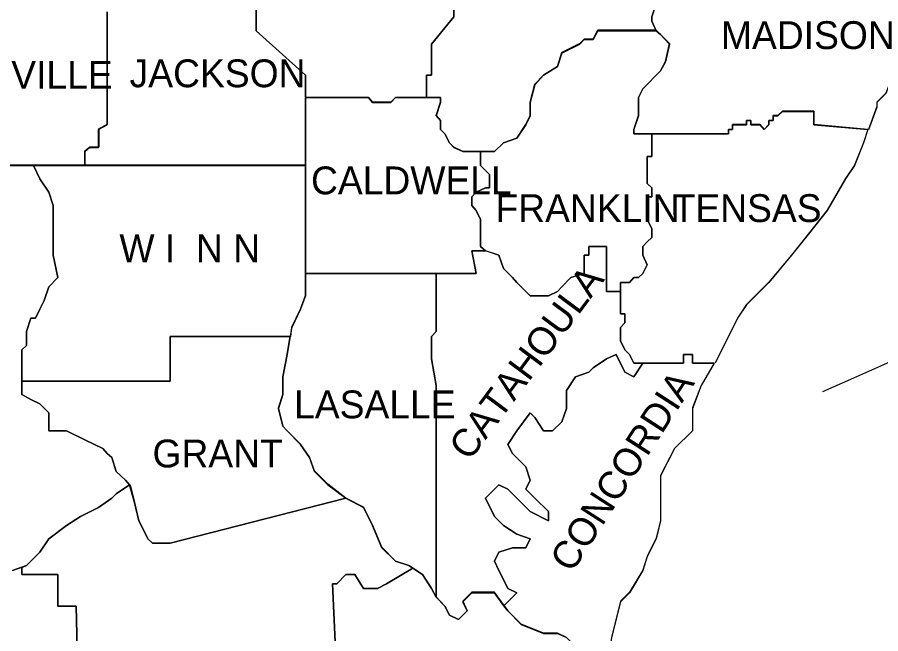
# Model space of a CAD drawing. Extents: x 0.19 to 2.82, y 0.04 to 1.79.
# Drawn here: x 2.2917 to 2.4368, y 1.594 to 1.6976 of the extents above; entities that cross this region are included whole.
import ezdxf

# ---------------------------------------------------------------- set-up
doc = ezdxf.new("R2010")
doc.units = 0
for name, color, linetype in [('Annotation', 7, 'Continuous'), ('Dist04', 7, 'Continuous'), ('Dist05', 7, 'Continuous'), ('Dist08', 7, 'Continuous'), ('Dist58', 7, 'Continuous'), ('Standard Info', 7, 'Continuous')]:
    doc.layers.add(name, color=color, linetype=linetype)

msp = doc.modelspace()

# ---------------------------------------------------------------- linework, layer by layer
at = {"layer": 'Annotation'}
msp.add_open_spline([(2.54158, 1.68565), (2.53002, 1.65102), (2.4977, 1.62743), (2.42701, 1.63461), (2.54158, 1.68565), (2.42701, 1.63461)], degree=3, dxfattribs=at)
at = {"layer": 'Dist04'}
for points in [[(2.30682, 1.6985), (2.30682, 1.67958), (2.3054, 1.67883), (2.3054, 1.6765), (2.3054, 1.67575), (2.3039, 1.67575), (2.30307, 1.67508), (2.30307, 1.67275)], [(2.30307, 1.67275), (2.27665, 1.67275)]]:
    msp.add_lwpolyline(points, dxfattribs=at)
at = {"layer": 'Dist05'}
for points in [[(2.43215, 1.709), (2.4324, 1.7075), (2.4339, 1.706), (2.4354, 1.70225), (2.43765, 1.69992), (2.43915, 1.69925), (2.44065, 1.69542), (2.43999, 1.69083), (2.43765, 1.68483), (2.43615, 1.68333), (2.43615, 1.68258), (2.43474, 1.67875)], [(2.30307, 1.67275), (2.30307, 1.67508), (2.3039, 1.67575), (2.3054, 1.67575), (2.3054, 1.6765), (2.3054, 1.67883), (2.30682, 1.67958), (2.30682, 1.6985)], [(2.39907, 1.69542), (2.38924, 1.69542), (2.38849, 1.69392), (2.38699, 1.69392), (2.38624, 1.69317), (2.38324, 1.69167), (2.38249, 1.68933), (2.38015, 1.68783), (2.37865, 1.68633), (2.3779, 1.68333), (2.3779, 1.68108), (2.37715, 1.67958), (2.37565, 1.67725), (2.3734, 1.6765), (2.3719, 1.675), (2.36957, 1.675), (2.36807, 1.675), (2.36657, 1.675), (2.36507, 1.67575), (2.36432, 1.6765), (2.36357, 1.678), (2.36282, 1.67875), (2.36282, 1.68025), (2.36207, 1.68108), (2.36282, 1.68333), (2.36282, 1.68408), (2.36049, 1.68408)], [(2.41124, 1.678), (2.39532, 1.678), (2.39532, 1.67875), (2.39607, 1.68108), (2.39607, 1.68258), (2.39607, 1.68408), (2.39682, 1.68558), (2.39982, 1.68858), (2.40065, 1.69017), (2.40132, 1.69317), (2.39982, 1.69467), (2.39907, 1.69542)], [(2.36049, 1.68408), (2.35524, 1.68408), (2.35449, 1.68333), (2.3514, 1.68333), (2.35074, 1.68408), (2.34015, 1.68408)], [(2.34015, 1.684), (2.34015, 1.67275)], [(2.42557, 1.67958), (2.42557, 1.68183), (2.42032, 1.68183), (2.41949, 1.68108), (2.41874, 1.68108), (2.41874, 1.68025), (2.41799, 1.68025), (2.41799, 1.67958), (2.41724, 1.67875), (2.41649, 1.67958), (2.41499, 1.67958), (2.41499, 1.68025), (2.41424, 1.68025), (2.41424, 1.67958), (2.4119, 1.67958), (2.4119, 1.67875), (2.41124, 1.67875), (2.41124, 1.678)], [(2.43465, 1.67875), (2.42557, 1.67958)], [(2.34015, 1.67275), (2.30307, 1.67275)]]:
    msp.add_lwpolyline(points, dxfattribs=at)
at = {"layer": 'Dist08'}
for points in [[(2.30307, 1.67275), (2.27665, 1.67275)], [(2.34015, 1.67275), (2.30307, 1.67275)], [(2.34015, 1.65458), (2.34015, 1.67275)], [(2.33765, 1.644), (2.33782, 1.6455), (2.33932, 1.6485), (2.34015, 1.65083), (2.34015, 1.65458)], [(2.36207, 1.60008), (2.36132, 1.60167), (2.35982, 1.60392), (2.35749, 1.60542), (2.35524, 1.60617), (2.35299, 1.6085), (2.3514, 1.61225), (2.3499, 1.61525), (2.3469, 1.61675), (2.3439, 1.61908), (2.34165, 1.62133), (2.34082, 1.62358), (2.33932, 1.62583), (2.33707, 1.62808), (2.33632, 1.62883), (2.33557, 1.63192), (2.33632, 1.63417), (2.33632, 1.63717), (2.33707, 1.64092), (2.33757, 1.644)], [(2.37349, 1.59875), (2.3719, 1.60092), (2.36807, 1.60092), (2.36657, 1.59942), (2.36732, 1.59783), (2.36582, 1.59633), (2.36432, 1.59708), (2.36357, 1.59858), (2.36207, 1.60017)], [(2.38057, 1.57817), (2.38249, 1.582), (2.38399, 1.5835), (2.38399, 1.5865), (2.38474, 1.5895), (2.38549, 1.59183), (2.38399, 1.59333), (2.38249, 1.59408), (2.38015, 1.59408), (2.3764, 1.59558), (2.37415, 1.59783), (2.37349, 1.59875)]]:
    msp.add_lwpolyline(points, dxfattribs=at)
at = {"layer": 'Dist58'}
msp.add_line((2.43465, 1.67875), (2.43465, 1.67875), dxfattribs=at)
for points in [[(2.36049, 1.68408), (2.36282, 1.68408), (2.36282, 1.68333), (2.36207, 1.68108), (2.36282, 1.68025), (2.36282, 1.67875), (2.36357, 1.678), (2.36432, 1.6765), (2.36507, 1.67575), (2.36657, 1.675), (2.36807, 1.675), (2.36957, 1.675), (2.3719, 1.675), (2.3734, 1.6765), (2.37565, 1.67725), (2.37715, 1.67958), (2.3779, 1.68108), (2.3779, 1.68333), (2.37865, 1.68633), (2.38015, 1.68783), (2.38249, 1.68933), (2.38324, 1.69167), (2.38624, 1.69317), (2.38699, 1.69392), (2.38849, 1.69392), (2.38924, 1.69542), (2.39907, 1.69542)], [(2.39907, 1.69542), (2.39982, 1.69467), (2.40132, 1.69317), (2.40065, 1.69017), (2.39982, 1.68858), (2.39682, 1.68558), (2.39607, 1.68408), (2.39607, 1.68258), (2.39607, 1.68108), (2.39532, 1.67875), (2.39532, 1.678), (2.41124, 1.678)], [(2.34015, 1.68408), (2.35074, 1.68408), (2.3514, 1.68333), (2.35449, 1.68333), (2.35524, 1.68408), (2.36049, 1.68408)], [(2.34015, 1.67275), (2.34015, 1.684)], [(2.41124, 1.678), (2.41124, 1.67875), (2.4119, 1.67875), (2.4119, 1.67958), (2.41424, 1.67958), (2.41424, 1.68025), (2.41499, 1.68025), (2.41499, 1.67958), (2.41649, 1.67958), (2.41724, 1.67875), (2.41799, 1.67958), (2.41799, 1.68025), (2.41874, 1.68025), (2.41874, 1.68108), (2.41949, 1.68108), (2.42032, 1.68183), (2.42557, 1.68183), (2.42557, 1.67958)], [(2.42557, 1.67958), (2.43465, 1.67875)], [(2.43465, 1.67875), (2.4339, 1.6765), (2.4324, 1.67275), (2.4309, 1.6705), (2.42782, 1.66517), (2.42482, 1.66142), (2.42182, 1.65758), (2.41799, 1.65308), (2.41424, 1.64933), (2.41274, 1.647), (2.40899, 1.63942)], [(2.34015, 1.65458), (2.34015, 1.67275)], [(2.33765, 1.644), (2.33782, 1.6455), (2.33932, 1.6485), (2.34015, 1.65083), (2.34015, 1.65458)], [(2.36207, 1.60008), (2.36132, 1.60167), (2.35982, 1.60392), (2.35749, 1.60542), (2.35524, 1.60617), (2.35299, 1.6085), (2.3514, 1.61225), (2.3499, 1.61525), (2.3469, 1.61675), (2.3439, 1.61908), (2.34165, 1.62133), (2.34082, 1.62358), (2.33932, 1.62583), (2.33707, 1.62808), (2.33632, 1.62883), (2.33557, 1.63192), (2.33632, 1.63417), (2.33632, 1.63717), (2.33707, 1.64092), (2.33757, 1.644)], [(2.40882, 1.63942), (2.40665, 1.63567), (2.40515, 1.63192), (2.40515, 1.62808), (2.40215, 1.62508), (2.39982, 1.62058), (2.39982, 1.613), (2.39907, 1.61), (2.39757, 1.60692), (2.39682, 1.60467), (2.39457, 1.60092), (2.39307, 1.59942), (2.39157, 1.59333), (2.39074, 1.588), (2.39157, 1.58425), (2.39232, 1.58275), (2.39382, 1.57975)], [(2.37349, 1.59875), (2.3719, 1.60092), (2.36807, 1.60092), (2.36657, 1.59942), (2.36732, 1.59783), (2.36582, 1.59633), (2.36432, 1.59708), (2.36357, 1.59858), (2.36207, 1.60017)], [(2.38057, 1.57817), (2.38249, 1.582), (2.38399, 1.5835), (2.38399, 1.5865), (2.38474, 1.5895), (2.38549, 1.59183), (2.38399, 1.59333), (2.38249, 1.59408), (2.38015, 1.59408), (2.3764, 1.59558), (2.37415, 1.59783), (2.37349, 1.59875)]]:
    msp.add_lwpolyline(points, dxfattribs=at)
at = {"layer": 'Standard Info'}
for p, q in [((2.33774, 1.645), (2.33757, 1.64392)), ((2.2909, 1.60458), (2.29249, 1.60517)), ((2.29249, 1.60517), (2.29265, 1.60517))]:
    msp.add_line(p, q, dxfattribs=at)
for points in [[(2.3569, 1.72125), (2.35982, 1.72033), (2.36282, 1.72033), (2.36432, 1.71883), (2.36582, 1.71733), (2.36807, 1.71733), (2.36882, 1.7165), (2.36807, 1.71583), (2.36732, 1.715), (2.36732, 1.712), (2.36582, 1.712), (2.36582, 1.709), (2.36732, 1.709), (2.36882, 1.70592), (2.36882, 1.70367), (2.36732, 1.70217), (2.36582, 1.70217), (2.36582, 1.69917), (2.36507, 1.69917), (2.36507, 1.69767), (2.36132, 1.69308), (2.36132, 1.68783), (2.36049, 1.68783), (2.36049, 1.68408)], [(2.34015, 1.68408), (2.34015, 1.68783), (2.33182, 1.69533), (2.33182, 1.70292), (2.33182, 1.70975)], [(2.40215, 1.7105), (2.40215, 1.709), (2.4029, 1.70825), (2.40132, 1.7075), (2.40065, 1.70592), (2.39982, 1.70525), (2.39907, 1.70442), (2.39832, 1.70292), (2.39832, 1.70217), (2.39832, 1.70142), (2.39907, 1.69992), (2.39832, 1.69767), (2.39832, 1.69692), (2.39907, 1.69533)], [(2.43215, 1.709), (2.4324, 1.7075), (2.4339, 1.70592), (2.4354, 1.70217), (2.43765, 1.69992), (2.43915, 1.69917), (2.44065, 1.69533), (2.43999, 1.69083), (2.43765, 1.68475), (2.43615, 1.68325), (2.43615, 1.6825), (2.43474, 1.67867)], [(2.36049, 1.68408), (2.36049, 1.68783), (2.36132, 1.68783), (2.36132, 1.69308), (2.36507, 1.69767), (2.36507, 1.69917), (2.36582, 1.69917), (2.36582, 1.70217), (2.36732, 1.70217), (2.36882, 1.70367), (2.36882, 1.70592)], [(2.39907, 1.69533), (2.39832, 1.69692), (2.39832, 1.69767), (2.39907, 1.69992), (2.39832, 1.70142), (2.39832, 1.70217), (2.39832, 1.70292), (2.39907, 1.70442), (2.39982, 1.70525), (2.40057, 1.70592)], [(2.33182, 1.70292), (2.33182, 1.69533), (2.34015, 1.68783), (2.34015, 1.68408)], [(2.30682, 1.6985), (2.30682, 1.67958), (2.3054, 1.67875), (2.3054, 1.6765), (2.3054, 1.67575), (2.3039, 1.67575), (2.30307, 1.675), (2.30307, 1.67267)], [(2.30307, 1.67267), (2.30307, 1.675), (2.30382, 1.67567), (2.30532, 1.67567), (2.30532, 1.6765), (2.30532, 1.67875), (2.30682, 1.6795), (2.30682, 1.69842)], [(2.39907, 1.69533), (2.38924, 1.69533), (2.38849, 1.69383), (2.38699, 1.69383), (2.38624, 1.69308), (2.38324, 1.69158), (2.38249, 1.68933), (2.38015, 1.68783), (2.37865, 1.68625), (2.3779, 1.68325), (2.3779, 1.681), (2.37715, 1.6795), (2.37565, 1.67725), (2.3734, 1.6765), (2.3719, 1.675), (2.36957, 1.675), (2.36807, 1.675), (2.36657, 1.675), (2.36507, 1.67567), (2.36432, 1.6765), (2.36357, 1.678), (2.36282, 1.67875), (2.36282, 1.68025), (2.36207, 1.681), (2.36282, 1.68325), (2.36282, 1.68408), (2.36049, 1.68408)], [(2.36957, 1.675), (2.3719, 1.675), (2.3734, 1.6765), (2.37565, 1.67725), (2.37715, 1.6795), (2.3779, 1.681), (2.3779, 1.68325), (2.37865, 1.68625), (2.38015, 1.68783), (2.38249, 1.68933), (2.38324, 1.69158), (2.38624, 1.69308), (2.38699, 1.69383), (2.38849, 1.69383), (2.38924, 1.69533), (2.39907, 1.69533)], [(2.41124, 1.678), (2.39532, 1.678), (2.39532, 1.67875), (2.39607, 1.681), (2.39607, 1.6825), (2.39607, 1.68408), (2.39682, 1.68558), (2.39982, 1.68858), (2.40065, 1.69008), (2.40132, 1.69308), (2.39982, 1.69467), (2.39907, 1.69533)], [(2.39907, 1.69533), (2.39982, 1.69467), (2.40132, 1.69308), (2.40065, 1.69008), (2.39982, 1.68858), (2.39682, 1.68558), (2.39607, 1.68408), (2.39607, 1.6825), (2.39607, 1.681), (2.39532, 1.67875), (2.39532, 1.678), (2.39832, 1.678)], [(2.36049, 1.68408), (2.35524, 1.68408), (2.35449, 1.68325), (2.3514, 1.68325), (2.35074, 1.68408), (2.34015, 1.68408)], [(2.34015, 1.68408), (2.35074, 1.68408), (2.3514, 1.68325), (2.35449, 1.68325), (2.35524, 1.68408), (2.36282, 1.68408), (2.36282, 1.68325), (2.36207, 1.681), (2.36282, 1.68025), (2.36282, 1.67875), (2.36357, 1.678), (2.36432, 1.6765), (2.36507, 1.67567), (2.36657, 1.675), (2.36807, 1.675), (2.36957, 1.675)], [(2.34015, 1.68392), (2.34015, 1.67267)], [(2.34015, 1.67267), (2.34015, 1.68383)], [(2.42557, 1.6795), (2.42557, 1.68175), (2.42032, 1.68175), (2.41949, 1.681), (2.41874, 1.681), (2.41874, 1.68025), (2.41799, 1.68025), (2.41799, 1.6795), (2.41724, 1.67875), (2.41649, 1.6795), (2.41499, 1.6795), (2.41499, 1.68025), (2.41424, 1.68025), (2.41424, 1.6795), (2.4119, 1.6795), (2.4119, 1.67875), (2.41124, 1.67875), (2.41124, 1.678)], [(2.41124, 1.678), (2.41124, 1.67875), (2.4119, 1.67875), (2.4119, 1.6795), (2.41424, 1.6795), (2.41424, 1.68025), (2.41499, 1.68025), (2.41499, 1.6795), (2.41649, 1.6795), (2.41724, 1.67875), (2.41799, 1.6795), (2.41799, 1.68025), (2.41874, 1.68025), (2.41874, 1.681), (2.41949, 1.681), (2.42032, 1.68175), (2.42557, 1.68175), (2.42557, 1.6795)], [(2.43465, 1.67875), (2.42557, 1.6795)], [(2.42557, 1.6795), (2.43465, 1.67875)], [(2.39832, 1.678), (2.39832, 1.67417), (2.39757, 1.67417), (2.39757, 1.66967), (2.39832, 1.66892), (2.39832, 1.66742), (2.39757, 1.66742), (2.39757, 1.66358), (2.39832, 1.66208), (2.39832, 1.66058), (2.39757, 1.65983), (2.39682, 1.65908), (2.39682, 1.65758), (2.39757, 1.656), (2.39682, 1.6545), (2.39607, 1.65383), (2.39532, 1.65383), (2.39457, 1.653), (2.39307, 1.653), (2.39307, 1.6515)], [(2.40882, 1.63942), (2.40515, 1.63942), (2.40515, 1.64092), (2.40365, 1.64092), (2.40365, 1.63942), (2.40215, 1.63942), (2.39757, 1.63942), (2.39532, 1.63942), (2.39457, 1.64092), (2.39382, 1.64167), (2.39307, 1.64317), (2.39307, 1.64392), (2.39307, 1.64542), (2.39382, 1.64625), (2.39382, 1.64775), (2.39307, 1.64775), (2.39307, 1.653), (2.39457, 1.653), (2.39532, 1.65383), (2.39607, 1.65383), (2.39682, 1.6545), (2.39757, 1.656), (2.39682, 1.65758), (2.39682, 1.65908), (2.39757, 1.65983), (2.39832, 1.66058), (2.39832, 1.66208), (2.39757, 1.66358), (2.39757, 1.66742), (2.39832, 1.66742), (2.39832, 1.66892), (2.39757, 1.66967), (2.39757, 1.67417), (2.39832, 1.67417), (2.39832, 1.678)], [(2.39832, 1.678), (2.41124, 1.678)], [(2.43465, 1.67875), (2.4339, 1.6765), (2.4324, 1.67267), (2.4309, 1.67042), (2.42782, 1.66508), (2.42482, 1.66133), (2.42182, 1.65758), (2.41799, 1.653), (2.41424, 1.64925), (2.41274, 1.647), (2.40899, 1.63942)], [(2.36957, 1.675), (2.36957, 1.67267), (2.37107, 1.67117), (2.37107, 1.66892), (2.3704, 1.66892), (2.36882, 1.66817), (2.36807, 1.66742), (2.36807, 1.66592), (2.36882, 1.66508), (2.36957, 1.66358), (2.36957, 1.66133), (2.36957, 1.65908), (2.3704, 1.65833)], [(2.39307, 1.6515), (2.39074, 1.6515), (2.39074, 1.65908), (2.38774, 1.65908), (2.38774, 1.65758), (2.38699, 1.65758), (2.38699, 1.656), (2.38699, 1.6545), (2.38474, 1.65383), (2.38324, 1.65225), (2.38249, 1.6515), (2.38099, 1.65075), (2.37949, 1.65075), (2.3779, 1.65075), (2.37715, 1.6515), (2.37565, 1.653), (2.3749, 1.65383), (2.3734, 1.65533), (2.37265, 1.65758), (2.3704, 1.65833), (2.36957, 1.65908), (2.36957, 1.66133), (2.36957, 1.66358), (2.36882, 1.66508), (2.36807, 1.66592), (2.36807, 1.66742), (2.36882, 1.66817), (2.3704, 1.66892), (2.37107, 1.66892), (2.37107, 1.67117), (2.36957, 1.67267), (2.36957, 1.675)], [(2.27657, 1.67267), (2.2944, 1.67267)], [(2.30307, 1.67267), (2.27665, 1.67267)], [(2.29249, 1.63642), (2.29249, 1.64167), (2.29324, 1.64242), (2.29324, 1.64317), (2.29324, 1.64475), (2.29399, 1.647), (2.29474, 1.647), (2.29549, 1.6485), (2.29624, 1.65), (2.29699, 1.65225), (2.29849, 1.65383), (2.29774, 1.65758), (2.29774, 1.66133), (2.29774, 1.66358), (2.29774, 1.66592), (2.29699, 1.66817), (2.29549, 1.67042), (2.2944, 1.67267)], [(2.2944, 1.67267), (2.29549, 1.67042), (2.29699, 1.66817), (2.29774, 1.66592), (2.29774, 1.66358), (2.29774, 1.66133), (2.29774, 1.65758), (2.29849, 1.65383), (2.29699, 1.65225), (2.29624, 1.65), (2.29549, 1.6485), (2.29474, 1.647), (2.29399, 1.647), (2.29324, 1.64475), (2.29324, 1.64317), (2.29324, 1.64242), (2.29249, 1.64167), (2.29249, 1.63417), (2.29399, 1.63333), (2.29549, 1.63258), (2.29699, 1.63108), (2.29699, 1.63033), (2.29699, 1.62808), (2.29999, 1.62808), (2.30307, 1.62658), (2.30607, 1.62508), (2.30682, 1.62425), (2.30757, 1.62358), (2.30832, 1.62125), (2.3099, 1.61975), (2.31057, 1.619)], [(2.2944, 1.67267), (2.34015, 1.67267)], [(2.34015, 1.67267), (2.30307, 1.67267)], [(2.34015, 1.67267), (2.34015, 1.65075), (2.33932, 1.6485), (2.33782, 1.64542), (2.33774, 1.645)], [(2.34015, 1.6545), (2.34015, 1.67267)], [(2.37115, 1.65808), (2.37265, 1.65758), (2.3734, 1.65533), (2.3749, 1.65383), (2.37565, 1.653), (2.37715, 1.6515), (2.3779, 1.65075), (2.37949, 1.65075), (2.38099, 1.65075), (2.38249, 1.6515), (2.38324, 1.65225), (2.38474, 1.65383), (2.38699, 1.6545), (2.38699, 1.656), (2.38699, 1.65758), (2.38774, 1.65758), (2.38774, 1.65908), (2.39074, 1.65908), (2.39074, 1.6515), (2.39307, 1.6515)], [(2.3704, 1.65833), (2.36807, 1.65833), (2.36882, 1.6545), (2.36207, 1.6545), (2.34015, 1.6545)], [(2.36207, 1.6545), (2.36882, 1.6545), (2.36807, 1.65833), (2.3704, 1.65833)], [(2.33765, 1.64392), (2.33782, 1.64542), (2.33932, 1.6485), (2.34015, 1.65075), (2.34015, 1.6545)], [(2.34015, 1.6545), (2.36207, 1.6545)], [(2.36207, 1.6545), (2.36207, 1.64475), (2.36132, 1.64392), (2.36132, 1.64017), (2.36207, 1.63567), (2.36207, 1.60008)], [(2.36207, 1.60008), (2.36207, 1.63567), (2.36132, 1.64017), (2.36132, 1.64392), (2.36207, 1.64475), (2.36207, 1.6545)], [(2.39307, 1.6515), (2.39307, 1.64775), (2.39382, 1.64775), (2.39382, 1.64625), (2.39307, 1.64542), (2.39307, 1.64392), (2.39307, 1.64317), (2.39382, 1.64167), (2.39457, 1.64092), (2.39532, 1.63942), (2.39682, 1.63942)], [(2.33757, 1.64392), (2.3174, 1.64392), (2.3174, 1.63642), (2.29699, 1.63642), (2.29249, 1.63642)], [(2.29249, 1.63642), (2.29699, 1.63642), (2.3174, 1.63642), (2.3174, 1.64392), (2.33757, 1.64392)], [(2.36207, 1.60008), (2.36132, 1.60158), (2.35982, 1.60392), (2.35749, 1.60542), (2.35524, 1.60617), (2.35299, 1.60842), (2.3514, 1.61217), (2.3499, 1.61517), (2.3469, 1.61675), (2.3439, 1.619), (2.34165, 1.62125), (2.34082, 1.62358), (2.33932, 1.62575), (2.33707, 1.62808), (2.33632, 1.62883), (2.33557, 1.63183), (2.33632, 1.63417), (2.33632, 1.63717), (2.33707, 1.64092), (2.33757, 1.64392)], [(2.33757, 1.64392), (2.33707, 1.64092), (2.33632, 1.63717), (2.33632, 1.63417), (2.33557, 1.63183), (2.33632, 1.62883), (2.33707, 1.62808), (2.33932, 1.62575), (2.34082, 1.62358), (2.34165, 1.62125), (2.3439, 1.619), (2.3469, 1.61675)], [(2.39682, 1.63942), (2.39532, 1.63717), (2.39382, 1.63792), (2.39232, 1.64092), (2.39074, 1.64017), (2.38849, 1.63867), (2.38774, 1.63792), (2.38549, 1.63717), (2.38399, 1.63483), (2.38399, 1.63333), (2.38399, 1.63183), (2.38324, 1.62958), (2.38165, 1.62808), (2.38015, 1.62808), (2.37865, 1.63033), (2.3779, 1.63108), (2.37565, 1.62808), (2.37415, 1.62575), (2.3749, 1.62425), (2.37715, 1.622), (2.3779, 1.61975), (2.37715, 1.61825), (2.37865, 1.61675), (2.38099, 1.6145), (2.38099, 1.61292), (2.3779, 1.6145), (2.37565, 1.61675), (2.37415, 1.61825), (2.37265, 1.619), (2.3704, 1.61675), (2.3719, 1.61367), (2.3734, 1.61217), (2.37565, 1.61067), (2.3779, 1.60992), (2.37715, 1.60842), (2.3749, 1.60842), (2.37265, 1.60767), (2.3719, 1.60617), (2.37265, 1.60458), (2.3734, 1.60308), (2.37415, 1.60158), (2.37565, 1.60083), (2.3734, 1.59858)], [(2.3734, 1.59858), (2.37565, 1.60083), (2.37415, 1.60158), (2.3734, 1.60308), (2.37265, 1.60458), (2.3719, 1.60617), (2.37265, 1.60767), (2.3749, 1.60842), (2.37715, 1.60842), (2.3779, 1.60992), (2.37565, 1.61067), (2.3734, 1.61217), (2.3719, 1.61367), (2.3704, 1.61675), (2.37265, 1.619), (2.37415, 1.61825), (2.37565, 1.61675), (2.3779, 1.6145), (2.38099, 1.61292), (2.38099, 1.6145), (2.37865, 1.61675), (2.37715, 1.61825), (2.3779, 1.61975), (2.37715, 1.622), (2.3749, 1.62425), (2.37415, 1.62575), (2.37565, 1.62808), (2.3779, 1.63108), (2.37865, 1.63033), (2.38015, 1.62808), (2.38165, 1.62808), (2.38324, 1.62958), (2.38399, 1.63183), (2.38399, 1.63333), (2.38399, 1.63483), (2.38549, 1.63717), (2.38774, 1.63792), (2.38849, 1.63867), (2.39074, 1.64017), (2.39232, 1.64092), (2.39382, 1.63792), (2.39532, 1.63717), (2.39682, 1.63942)], [(2.39682, 1.63942), (2.40215, 1.63942), (2.40365, 1.63942), (2.40365, 1.64092), (2.40515, 1.64092), (2.40515, 1.63942), (2.40882, 1.63942)], [(2.40882, 1.63942), (2.40665, 1.63567), (2.40515, 1.63183), (2.40515, 1.62808), (2.40215, 1.62508), (2.39982, 1.6205), (2.39982, 1.61292), (2.39907, 1.60992), (2.39757, 1.60692), (2.39682, 1.60458), (2.39457, 1.60083), (2.39307, 1.59933), (2.39157, 1.59333), (2.39074, 1.588), (2.39157, 1.58425), (2.39232, 1.58267), (2.39382, 1.57967)], [(2.3469, 1.61675), (2.3174, 1.60917), (2.3144, 1.60917), (2.31365, 1.60992), (2.3129, 1.61142), (2.31215, 1.61292), (2.3114, 1.616), (2.31057, 1.619), (2.3099, 1.61975), (2.30832, 1.62125), (2.30757, 1.62358), (2.30682, 1.62425), (2.30607, 1.62508), (2.30307, 1.62658), (2.29999, 1.62808), (2.29699, 1.62808), (2.29699, 1.63033), (2.29699, 1.63108), (2.29549, 1.63258), (2.29399, 1.63333), (2.29249, 1.63417), (2.29249, 1.63642)], [(2.31057, 1.619), (2.30832, 1.6175), (2.30757, 1.61675), (2.30532, 1.61517), (2.30232, 1.61367), (2.29999, 1.61217), (2.29699, 1.60992), (2.29549, 1.60767), (2.29324, 1.60542), (2.2909, 1.60458)], [(2.2909, 1.60458), (2.29324, 1.60542), (2.29549, 1.60767), (2.29699, 1.60992), (2.29999, 1.61217), (2.30232, 1.61367), (2.30532, 1.61517), (2.30757, 1.61675), (2.30832, 1.6175), (2.31057, 1.619)], [(2.29265, 1.60517), (2.29324, 1.60542), (2.29549, 1.60767), (2.29699, 1.60992), (2.29999, 1.61217), (2.30232, 1.61367), (2.30532, 1.61517), (2.30757, 1.61675), (2.30832, 1.6175), (2.31057, 1.619)], [(2.31065, 1.619), (2.3114, 1.616), (2.31215, 1.61292), (2.3129, 1.61142), (2.31365, 1.60992), (2.3144, 1.60917), (2.3174, 1.60917), (2.3469, 1.61675)], [(2.3469, 1.61675), (2.3499, 1.61517), (2.3514, 1.61217), (2.35299, 1.60842), (2.35524, 1.60617), (2.35749, 1.60542), (2.35815, 1.605)], [(2.29249, 1.60517), (2.29249, 1.60392), (2.29849, 1.60392), (2.29849, 1.59858), (2.30157, 1.59858), (2.30232, 1.56758)], [(2.29249, 1.60517), (2.29249, 1.60392), (2.29849, 1.60392), (2.29849, 1.59858), (2.30157, 1.59858), (2.30232, 1.56758)], [(2.30232, 1.56758), (2.30157, 1.59858), (2.29849, 1.59858), (2.29849, 1.60392), (2.29249, 1.60392), (2.29249, 1.60517)], [(2.29249, 1.60508), (2.29249, 1.60392), (2.29849, 1.60392), (2.29849, 1.59858), (2.30157, 1.59858), (2.30232, 1.56758)], [(2.35815, 1.605), (2.35374, 1.60233), (2.35224, 1.60158), (2.35074, 1.60158), (2.3499, 1.60158), (2.3484, 1.60392), (2.3469, 1.60392), (2.3454, 1.60233), (2.34465, 1.60233), (2.3454, 1.5865), (2.34615, 1.57967), (2.3484, 1.57283), (2.3424, 1.57283)], [(2.3424, 1.57283), (2.3484, 1.57283), (2.34615, 1.57967), (2.3454, 1.5865), (2.34465, 1.60233), (2.3454, 1.60233), (2.3469, 1.60392), (2.3484, 1.60392), (2.3499, 1.60158), (2.35074, 1.60158), (2.35224, 1.60158), (2.35374, 1.60233), (2.35815, 1.605)], [(2.35815, 1.605), (2.35982, 1.60392), (2.36132, 1.60158), (2.36207, 1.60008), (2.36357, 1.59858), (2.36432, 1.59708), (2.36582, 1.59633), (2.36732, 1.59783), (2.36657, 1.59933), (2.36807, 1.60083), (2.3719, 1.60083), (2.37415, 1.59783), (2.3764, 1.5955), (2.38015, 1.594), (2.38249, 1.594), (2.38399, 1.59333), (2.38549, 1.59175), (2.38474, 1.5895), (2.38399, 1.5865), (2.38399, 1.58342), (2.38249, 1.58192), (2.38065, 1.57833)], [(2.37349, 1.59867), (2.3719, 1.60083), (2.36807, 1.60083), (2.36657, 1.59933), (2.36732, 1.59783), (2.36582, 1.59633), (2.36432, 1.59708), (2.36357, 1.59858), (2.36207, 1.60017)], [(2.38057, 1.57817), (2.38249, 1.58192), (2.38399, 1.58342), (2.38399, 1.5865), (2.38474, 1.5895), (2.38549, 1.59175), (2.38399, 1.59333), (2.38249, 1.594), (2.38015, 1.594), (2.3764, 1.5955), (2.37415, 1.59783), (2.37349, 1.59867)]]:
    msp.add_lwpolyline(points, dxfattribs=at)

# ---------------------------------------------------------------- texts
for s, p in [('MADISON', (2.40996, 1.69225)), ('JACKSON', (2.31058, 1.68583)), ('BIENVILLE', (2.27608, 1.68558)), ('CALDWELL', (2.34106, 1.66783)), ('FRANKLIN', (2.37206, 1.66316)), ('TENSAS', (2.40183, 1.66317)), ('W I  N N', (2.30886, 1.65642)), ('LASALLE', (2.33822, 1.63017)), ('GRANT', (2.31442, 1.62192))]:
    msp.add_text(s, height=0.004679, dxfattribs=at).set_placement(p)
for s, rotation, p in [('CATAHOULA', 53.3344, (2.36768, 1.62284)), ('CONCORDIA', 57.0945, (2.38489, 1.60403))]:
    msp.add_text(s, height=0.004679, rotation=rotation, dxfattribs=at).set_placement(p)

doc.saveas('drawing.dxf')
